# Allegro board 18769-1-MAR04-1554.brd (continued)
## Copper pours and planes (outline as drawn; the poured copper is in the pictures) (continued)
Net_26475 on BOTTOM_-MB (solid shape): 101.29,77.78 101.29,77.34 101.66,76.96 103.77,76.96 103.9,76.83 103.9,74.27 103.85,74.21 101.61,74.21 100.71,73.3 100.47,73.3 100.44,73.3 100.41,73.28 100.38,73.26 100.36,73.25 100.03,73.25 99.94,73.16 98.11,73.16 97.99,73.28 97.99,74.2 98.82,74.2 98.82,73.95 99.07,73.95 99.09,73.95 100.01,73.95 100.3,73.81 100.56,73.81 100.56,74.07 100.26,74.2 100.01,74.2 100.01,73.95 99.35,73.95 99.35,74.2 99.09,74.2 99.07,74.2 97.99,74.2 97.99,76.54 97.95,76.58 97.95,76.75 99.29,78.08 100.99,78.08
Net_26477 on BOTTOM_-MB (solid shape): 64.1,76 64.1,74.49 63.69,74.09 63.68,74.09 63.37,73.77 62.39,73.77 61.43,74.73 61.43,75.33 63.84,75.33 63.84,75.58 63.59,75.58 63.59,75.33 62.93,75.33 62.93,75.58 62.67,75.58 62.67,75.33 61.43,75.33 61.43,75.87 61.81,76.26 63.84,76.26
Net_26478 on BOTTOM_-MB (solid shape): outline of 206 points within 36.82,73.97 57.29,82.05
Net_26479 on BOTTOM_-MB (solid shape): 59.14,75.37 60.29,75.37 60.41,75.24 60.41,74.48 60.4,74.46 60.4,74.35 60.22,74.18 58.45,74.18 58.45,74.39 58.14,74.69 57.84,74.69 57.84,74.73 57.72,74.73 57.63,74.82 58.82,74.82 58.82,75.07 58.57,75.07 58.57,74.82 57.63,74.82 57.6,74.86 55.72,74.86 55.5,75.08 55.5,75.61 57.91,75.61 57.91,75.86 57.65,75.86 57.65,75.61 55.5,75.61 55.5,75.67 55.86,76.03 58.48,76.03
Net_26480 on BOTTOM_-MB (solid shape): 67.4,82.1 67.53,81.97 71.34,81.97 71.46,81.84 71.46,80.57 69.43,78.54 68.97,78.54 68.8,78.36 68.8,75.85 68.69,75.75 66.13,75.75 66,75.87 66,79.38 66,79.39 66.03,79.55 66,79.71 66,79.71 66,82.1 66.26,82.35 66.26,83.37 66.38,83.49 67.4,83.49
Net_26481 on BOTTOM_-MB (solid shape): 88.34,83.81 88.34,83.12 88.34,83.11 88.34,82.82 88.54,82.62 88.54,82.55 88.61,82.55 88.74,82.42 92.33,82.42 92.8,81.95 92.8,78.3 93.33,77.77 93.33,76.64 92.85,76.16 90.07,76.16 89.96,76.27 89.96,79.35 88.5,80.81 87.66,80.81 87.24,81.23 87.24,83.41 87.69,83.86 88.29,83.86
Net_26482 on BOTTOM_-MB (solid shape): 36.18,80.8 36.49,80.8 36.64,80.65 36.64,80.55 36.72,80.47 37.5,80.47 37.58,80.4 37.58,79.79 37.22,79.43 36.79,79.43 36.64,79.28 36.64,78.19 37.17,77.65 37.81,77.65 37.93,77.53 37.93,76.51 37.81,76.38 36.28,76.38 36.16,76.51 36.16,77.27 35.65,77.78 33.24,77.78 32.83,78.19 32.83,80.62 33.03,80.83 36.16,80.83
Net_26483 on BOTTOM_-MB (solid shape): 135.67,77.63 135.67,76.78 135.47,76.58 135.16,76.58 135.06,76.68 134.31,76.68 134.22,76.59 133.77,76.59 133.65,76.71 133.65,77.31 134.09,77.31 134.18,77.31 134.18,77.06 134.43,77.06 134.43,77.31 134.35,77.31 134.35,77.57 134.09,77.57 134.09,77.31 133.65,77.31 133.65,77.95 133.69,77.99 135.31,77.99
Net_26484 on BOTTOM_-MB (solid shape): 133.61,78.78 133.61,78.15 133.52,78.06 133.52,76.71 133.43,76.61 132.99,76.61 132.85,76.75 132.85,76.97 132.69,77.13 132.65,77.16 132.61,77.17 132.56,77.18 132.18,77.18 132.13,77.17 132.1,77.16 132.04,77.12 131.94,77.02 131.4,77.02 131.28,77.14 131.28,77.31 133.13,77.31 133.13,77.57 132.87,77.57 132.87,77.31 131.28,77.31 131.28,77.56 131.55,77.82 133.13,77.82 133.13,78.08 132.87,78.08 132.87,77.82 131.55,77.82 131.82,78.1 132.47,78.1 132.73,78.36 132.73,78.66 132.9,78.82 133.57,78.82
Net_26485 on BOTTOM_-MB (solid shape): 128.66,81.17 128.66,80.85 128.63,80.85 128.63,79.07 128.63,79.07 128.63,78.94 129.25,78.33 129.85,78.33 130.01,78.17 130.01,77.62 129.92,77.53 129.92,76.85 129.71,76.64 128.84,76.64 128.07,77.4 129.22,77.4 129.22,77.15 129.48,77.15 129.48,77.4 129.58,77.5 129.58,77.76 129.33,77.76 129.33,77.5 129.22,77.4 128.07,77.4 127.32,78.15 127.34,78.17 127.37,78.21 127.4,78.26 127.42,78.31 127.43,78.37 127.43,78.42 127.43,78.47 127.41,78.53 127.39,78.58 127.37,78.62 127.33,78.67 127.3,78.7 127.25,78.74 127.2,78.76 127.15,78.78 127.1,78.79 127.06,78.79 127.03,78.8 127.01,78.82 126.99,78.85 126.98,78.87 126.98,78.92 126.96,78.98 126.94,79.03 126.91,79.08 126.87,79.13 126.85,79.15 126.85,79.7 126.94,79.78 126.94,80.75 127.06,80.88 127.06,81.17 127.29,81.4 128.44,81.4
Net_26486 on BOTTOM_-MB (solid shape): outline of 133 points within 129.45,77.58 136.51,81.74
Net_26487 on BOTTOM_-MB (solid shape): outline of 85 points within 98.49,78.24 105.73,82.43
Net_26488 on BOTTOM_-MB (solid shape): 139.8,79.78 139.91,79.67 139.91,79.24 139.78,79.11 139.53,79.11 139.51,79.1 139.47,79.1 139.47,79.05 139.4,78.98 139.4,78.53 139.28,78.41 139.12,78.41 139.11,78.42 138.96,78.46 138.8,78.42 138.79,78.41 138.42,78.41 138.3,78.53 138.3,79.59 138.29,79.6 138.29,79.68 138.39,79.78 138.94,79.78
Net_26489 on BOTTOM_-MB (solid shape): 129.77,80.37 132.14,80.37 132.67,79.84 133.49,79.84 133.57,79.76 133.57,79.48 133.55,79.46 132.63,79.46 132,78.83 131.96,78.83 131.91,78.82 131.86,78.8 131.82,78.77 131.78,78.74 131.75,78.7 131.72,78.65 131.71,78.6 131.7,78.55 131.7,78.53 131.67,78.5 129.88,78.5 129.86,78.52 129.39,78.52 128.95,78.97 128.95,79.23 131.5,79.23 131.51,79.23 131.76,79.23 131.76,79.48 131.51,79.48 131.5,79.49 131.25,79.49 131.25,79.23 130.59,79.23 130.59,79.49 130.33,79.49 130.33,79.23 128.95,79.23 128.95,79.44 128.93,79.45 128.93,79.86 130.31,79.86 130.31,80.11 130.06,80.11 130.06,79.86 129.8,79.86 129.8,80.11 129.55,80.11 129.55,79.86 128.93,79.86 128.93,80.58 129.03,80.68 129.46,80.68
Net_26490 on BOTTOM_-MB (solid shape): 39.97,80.73 39.97,79.51 39.69,79.23 39.69,78.54 39.64,78.49 38.6,78.49 38.44,78.64 38.44,80.95 38.6,81.11 39.59,81.11
Net_26491 on BOTTOM_-MB (solid shape): 40.98,80.57 40.98,79.56 40.91,79.5 40.91,78.57 40.83,78.49 40.35,78.49 40.3,78.54 40.3,79.33 40.2,79.43 40.2,80.61 40.37,80.78 40.77,80.78
Net_26492 on BOTTOM_-MB (solid shape): outline of 111 points within 67.73,78.41 86.24,88.21
Net_26493 on BOTTOM_-MB (solid shape): 138.07,80.45 138.07,78.83 137.81,78.57 137.38,78.57 137.21,78.74 137.2,78.79 137.2,78.83 137.2,79.25 137.14,79.31 135.87,79.31 135.87,79.31 135.76,79.31 135.66,79.41 134.71,79.41 134.66,79.47 134.66,79.78 134.7,79.82 135.41,79.82 135.44,79.85 135.52,79.85 135.52,79.93 135.71,80.12 135.71,80.42 135.79,80.5 138.02,80.5
Net_26494 on BOTTOM_-MB (solid shape): outline of 1060 points within 167.93,78.93 178.76,86.34
Net_26495 on BOTTOM_-MB (solid shape): 126.94,81.56 126.94,80.93 126.81,80.8 126.81,79.84 126.66,79.68 125.74,79.68 125.01,80.42 125.01,81.62 125.08,81.69 126.81,81.69
Net_26496 on BOTTOM_-MB (solid shape): 138.49,81.91 140.43,81.91 140.66,81.68 140.68,81.63 140.68,80.75 140.05,80.11 138.33,80.11 138.24,80.2 138.24,80.55 138.03,80.76 136.03,80.76 135.89,80.9 139.46,80.9 139.52,80.87 139.78,80.87 139.78,81.12 139.52,81.12 139.46,81.15 139.21,81.15 139.21,80.9 138.55,80.9 138.55,81.15 138.29,81.15 138.29,80.9 135.89,80.9 135.59,81.2 135.59,82.34 135.78,82.53 137.88,82.53
Net_26497 on BOTTOM_-MB (solid shape): outline of 89 points within 109.21,79.92 117.82,87.37
Net_26498 on BOTTOM_-MB (solid shape): 122.11,84.26 122.11,82.57 122.18,82.5 122.16,82.47 122.25,81.99 122.74,81.99 122.75,82 122.79,82 123,82.21 123.13,82.21 123.15,82.22 123.58,82.22 123.59,82.23 123.97,82.23 123.98,82.22 124,82.25 124,82.77 124.1,82.86 127.59,82.86 127.75,82.71 127.75,81.92 127.57,81.74 126.99,81.74 126.99,81.81 126.87,81.81 126.86,81.82 125.03,81.82 125.02,81.81 124.93,81.81 124.93,81.72 124.88,81.67 124.88,80.96 124.5,80.58 119.48,80.58 119.09,80.98 119.09,84.23 119.39,84.54 121.83,84.54
Net_26499 on BOTTOM_-MB (solid shape): 100.5,86.03 100.79,86.03 100.81,86.01 100.81,85.5 101.21,85.11 101.21,84.44 101.09,84.32 100.57,84.32 100.56,84.3 100.49,84.3 100.49,84.23 100.15,83.89 100.15,82.83 99.85,82.53 99.16,82.53 98.21,81.57 95.12,81.57 94.89,81.8 94.89,82.02 95.68,82.8 96.25,82.8 96.53,83.08 96.53,84.6 96.79,84.86 100.83,84.86 100.83,85.11 100.58,85.11 100.58,84.86 96.79,84.86 97.3,85.38 98.64,85.38 98.8,85.54 98.8,85.85 99.06,86.11 100.42,86.11
Net_26500 on BOTTOM_-MB (solid shape): 90.11,86.06 90.11,84.82 90.16,84.76 90.46,84.76 90.47,84.75 92.74,84.75 93.26,84.23 95.75,84.23 95.95,84.03 95.95,83.29 94.49,81.83 93.9,81.83 93.13,82.61 88.73,82.61 88.61,82.73 88.61,83.2 93.71,83.2 93.71,83.45 94.37,83.45 94.37,83.2 94.63,83.2 94.66,83.21 94.92,83.21 94.92,83.47 94.66,83.47 94.63,83.45 93.46,83.45 93.46,83.2 88.61,83.2 88.61,83.24 88.53,83.32 88.53,83.85 89.17,83.85 89.17,84.51 88.53,84.51 88.53,86.11 88.66,86.24 89.93,86.24
Net_26501 on BOTTOM_-MB (solid shape): 131.8,83.17 131.8,82.33 131.54,82.07 129.05,82.07 128.69,82.43 128.69,83.13 128.86,83.3 131.41,83.3 131.41,83.33 131.65,83.33
Net_26502 on BOTTOM_-MB (solid shape): 73.16,86.74 75.87,86.74 77.15,85.46 78.67,85.46 78.94,85.19 78.94,84.24 78.92,84.21 78.9,84.15 78.88,84.09 78.87,84.03 78.87,83.97 78.88,83.91 78.9,83.85 78.92,83.79 78.94,83.76 78.94,83.35 78.92,83.32 78.9,83.27 78.88,83.21 78.87,83.15 78.87,83.09 78.88,83.03 78.89,82.97 78.92,82.91 78.94,82.87 78.94,82.82 78.82,82.71 76.57,82.71 75.52,83.76 73.15,83.76 72.41,84.5 73.49,84.5 73.49,84.75 74.15,84.75 74.15,84.5 74.41,84.5 74.46,84.5 75.63,84.5 75.63,84.76 75.37,84.76 75.37,84.5 74.71,84.5 74.71,84.76 74.46,84.76 74.41,84.75 73.24,84.75 73.24,84.5 72.41,84.5 72.24,84.67 69.62,84.67 69.49,84.8 69.49,85.63 76.46,85.62 76.46,85.88 76.2,85.88 76.2,85.62 75.11,85.62 75.11,85.88 74.59,85.88 74.59,85.63 73.5,85.63 73.5,85.88 73.24,85.88 73.24,85.63 69.49,85.63 69.49,85.84 69.65,86 70.92,86 70.98,86.06 71.05,86.06 71.05,86.85 71.11,86.91 72.99,86.91
Net_26503 on BOTTOM_-MB (solid shape): 128.32,85.78 132.01,85.78 132.26,85.53 132.26,84.31 131.52,83.57 131.41,83.57 131.41,83.61 128.87,83.61 128.87,83.57 128.38,83.57 128.13,83.32 124.09,83.32 124,83.41 124,84.55 124.15,84.7 126.89,84.7 126.89,84.71 126.92,84.74 126.99,84.74 126.99,84.8 127.09,84.91 127.09,85.04 131.79,85.04 131.79,85.3 131.53,85.3 131.53,85.04 127.09,85.04 127.09,86.38 127.15,86.44 127.67,86.44
Net_26504 on BOTTOM_-MB (solid shape): 138.52,85.63 138.52,85.4 138.44,85.33 137.66,85.33 137.66,85.24 137.6,85.17 137.6,84.34 137.89,84.04 137.89,83.49 137.75,83.35 134.65,83.35 134.51,83.49 134.51,84.94 134.77,85.2 136.97,85.2 137.02,85.26 137.08,85.26 137.08,85.32 137.43,85.67 137.48,85.67 137.52,85.68 138.47,85.68
Net_26505 on BOTTOM_-MB (solid shape): 139.41,86.42 139.41,85.53 139.46,85.47 139.46,85.27 140.05,85.27 140.3,85.02 140.3,84.51 140.04,84.26 139.41,84.26 138.65,85.02 138.65,86.16 138.62,86.18 138.62,86.33 137.85,86.33 137.76,86.42 137.76,86.67 137.88,86.8 139.03,86.8
Net_26506 on BOTTOM_-MB (solid shape): 92.83,87.08 94.09,87.08 94.17,87.16 94.17,87.16 94.27,87.26 94.65,87.26 94.65,87.22 94.97,87.22 95.06,87.12 95.06,86.87 96.29,85.64 96.29,84.98 95.97,84.67 93.49,84.67 93.28,84.88 90.52,84.88 90.28,85.13 90.28,85.31 93.71,85.31 93.71,85.56 94.37,85.56 94.37,85.31 94.63,85.31 94.66,85.32 95.83,85.32 95.83,85.58 95.58,85.58 95.58,85.32 94.92,85.32 94.92,85.58 94.66,85.58 94.63,85.56 93.46,85.56 93.46,85.31 90.28,85.31 90.28,86.12 90.43,86.27 91.85,86.27 92.01,86.43 92.01,87.17 92.1,87.26 92.65,87.26
Net_26507 on BOTTOM_-MB (solid shape): 139.43,88.52 139.43,87.25 139.18,87 137.73,87 137.68,86.95 137.68,86.95 137.56,86.82 137.56,86.81 137.12,86.38 137.12,86.31 137.09,86.27 137.06,86.22 137.04,86.17 137.03,86.12 137.02,86.07 137.02,86.01 137.03,85.96 137.05,85.9 137.07,85.86 137.1,85.81 137.12,85.79 137.12,85.57 136.93,85.37 133.72,85.37 133.41,85.68 133.41,86.73 136.11,86.73 136.11,86.99 136.77,86.99 136.77,86.73 137.02,86.73 137.3,87.09 137.3,87.13 139.04,87.13 139.04,87.38 138.79,87.38 138.79,87.13 137.3,87.13 137.3,87.34 137.05,87.34 136.77,86.99 135.85,86.99 135.85,86.73 133.41,86.73 133.41,86.98 133.68,87.25 135.85,87.25 135.88,87.28 135.98,87.38 135.98,87.61 136.25,87.88 137.25,87.88 137.26,87.89 138.79,87.89 138.79,87.64 139.04,87.64 139.04,87.89 139.09,87.89 139.09,88.15 138.84,88.15 138.84,87.89 137.26,87.89 137.46,88.09 137.98,88.09 138.47,88.59 139.37,88.59
Net_26508 on BOTTOM_-MB (solid shape): 126.12,88.02 126.12,86.98 125.93,86.78 125.93,86.67 125.9,86.64 125.9,85.82 125.86,85.79 125.43,85.79 125.43,85.8 125.31,85.93 125.31,86.29 125.4,86.38 125.4,86.49 125.4,87.03 125.25,87.18 124.07,87.18 123.95,87.3 123.95,87.41 125.68,87.41 125.68,87.67 125.43,87.67 125.43,87.41 123.95,87.41 123.95,87.86 124.02,87.93 124.57,87.93 124.61,87.93 124.67,87.93 124.71,87.93 125.28,87.93 125.42,88.06 126.07,88.06
Net_26509 on BOTTOM_-MB (solid shape): 101.7,87.52 101.7,86.98 101.52,86.79 100.92,86.79 100.84,86.71 100.84,86.59 100.84,86.59 100.84,86.3 100.77,86.24 99.01,86.24 98.49,85.71 96.42,85.71 95.3,86.83 95.29,86.83 95.19,86.94 95.19,87.19 95.53,87.19 95.55,87.21 99.84,87.21 99.84,87.15 99.86,87.1 99.88,87.05 99.91,87 99.94,86.96 99.99,86.92 100.03,86.89 100.08,86.87 100.14,86.85 100.19,86.84 100.25,86.84 100.3,86.85 100.36,86.87 100.41,86.89 100.45,86.92 100.49,86.96 100.53,87 100.56,87.05 100.58,87.1 100.59,87.15 100.6,87.21 100.6,87.26 100.59,87.3 101.31,87.3 101.31,87.56 101.05,87.56 101.05,87.3 100.59,87.3 100.59,87.32 100.57,87.37 100.55,87.42 100.51,87.47 100.47,87.51 100.43,87.54 100.38,87.57 100.33,87.59 100.27,87.6 100.22,87.6 100.16,87.6 100.11,87.59 100.06,87.57 100.01,87.54 99.96,87.51 99.93,87.47 99.89,87.42 99.87,87.37 99.85,87.32 99.84,87.26 99.84,87.21 95.55,87.21 95.62,87.28 95.97,87.28 96.54,87.85 101.38,87.85
Net_26510 on BOTTOM_-MB (solid shape): 140.3,88.5 140.3,88.4 140.42,88.27 140.45,88.25 140.58,88.12 140.91,88.12 141.01,88.02 141.01,87.61 140.85,87.46 140.45,87.46 140.2,87.2 140.2,86.77 140.32,86.65 140.32,86.42 140.24,86.34 139.62,86.34 139.54,86.42 139.54,87.18 139.56,87.2 139.56,87.89 140.11,87.89 140.11,87.64 140.36,87.64 140.36,87.89 140.31,87.89 140.31,88.15 140.06,88.15 140.06,87.89 139.56,87.89 139.56,88.62 139.62,88.68 140.12,88.68
Net_26511 on BOTTOM_-MB (solid shape): 131.36,88.3 131.36,88.24 131.3,88.15 131.19,88.16 130.57,87.86 131.19,87.57 131.3,87.58 131.36,87.49 131.36,86.52 131.25,86.42 128.05,86.42 127.9,86.57 127.9,87 127.97,87.07 127.97,87.69 128.04,87.94 127.92,88.17 127.91,88.2 127.92,88.24 128.21,88.52 131.13,88.52
Net_26512 on BOTTOM_-MB (solid shape): 116.43,88.51 116.43,88.3 116.41,88.26 116.39,88.2 116.38,88.15 116.38,88.09 116.39,88.03 116.4,87.98 116.43,87.93 116.46,87.88 116.5,87.84 116.54,87.8 116.59,87.77 116.64,87.75 116.7,87.73 116.74,87.73 116.75,87.72 119.4,87.72 120.32,88.64 120.76,88.64 120.9,88.5 120.9,88.02 120.61,87.74 120.61,86.57 120.49,86.44 118.42,86.44 117.66,87.2 116.64,87.2 116.09,87.76 112.62,87.76 112.11,87.25 111.8,87.25 111.55,87.5 111.34,87.5 110.51,87.5 110.17,87.5 110.11,87.51 109.59,87.51 109.31,87.79 110.33,87.79 110.34,87.79 111.51,87.79 111.51,88.04 111.25,88.04 111.25,87.79 110.59,87.79 110.59,88.04 110.34,88.04 110.33,88.04 110.08,88.04 110.08,87.79 109.31,87.79 109.23,87.88 109.23,88.52 109.43,88.72 116.23,88.72
Net_26513 on BOTTOM_-MB (solid shape): 79.77,88.27 79.77,86.95 79.62,86.8 78.89,86.8 78.81,86.89 73.27,86.89 72.86,87.3 76.46,87.3 76.46,87.51 79.09,87.51 79.09,87.5 79.09,87.25 79.35,87.25 79.35,87.5 79.34,87.51 79.34,87.77 79.09,87.77 79.09,87.51 76.46,87.51 76.46,87.56 76.2,87.56 76.2,87.3 75.11,87.3 75.11,87.56 74.59,87.56 74.59,87.3 73.5,87.3 73.5,87.56 73.24,87.56 73.24,87.3 72.86,87.3 72.74,87.42 72.74,87.6 72.74,87.62 72.73,87.66 72.71,87.7 72.69,87.73 72.65,87.76 72.65,88.02 79.34,88.02 79.34,88.28 79.09,88.28 79.09,88.02 72.65,88.02 72.65,88.04 73.09,88.48 79.56,88.48
Net_26514 on BOTTOM_-MB (solid shape): 135.75,88.4 135.75,87.71 135.62,87.59 134.05,87.59 134.05,88.5 134.15,88.6 134.18,88.6 134.35,88.78 135.37,88.78
OVP_UVP_REF_VDD on TOP: 155.74,30.54 155.88,30.67 156.13,30.67 156.34,30.47 156.34,30.23 156.68,29.88 156.68,29.51 156.59,29.41 156.59,29.16 156.47,29.04 155.98,29.04 155.74,29.28 ; 1 cut-out
OVP_UVP_REF_VDD on L3: 156.22,30.18 155.85,30.18 155.74,30.29 155.74,30.63 158.06,32.95 160.72,32.95 161.85,31.81 161.85,31.18 161.74,31.06 161.37,31.06 159.94,32.49 158.42,32.49 156.63,30.7 156.43,30.7 156.36,30.64 156.36,30.33
PCH_POPIRCOMP on TOP: 102.99,49.41 102.78,49.62 102.78,50.06 102.57,50.27 102.57,50.64 102.62,50.69 103.05,50.69 103.2,50.54 103.2,50.28 103.42,50.06 103.42,49.63 103.2,49.41
PS_ID_R2 on BOTTOM: 24.8,50.37 24.72,50.44 24.72,51.41 24.51,51.63 23.1,51.63 22.82,51.9 22.82,52.57 23.37,53.12 28.23,53.12 28.56,52.79 28.56,51.39 28.02,50.85 26.9,50.85 26.41,50.37
PWR_1D05V_PH on BOTTOM: 119.48,80.58 119.09,80.98 119.09,84.23 119.39,84.54 121.83,84.54 122.11,84.26 122.11,82.57 122.45,82.22 123.58,82.22 123.59,82.23 123.97,82.23 123.98,82.22 124,82.25 124,82.77 124.1,82.86 127.59,82.86 127.75,82.71 127.75,81.92 127.57,81.74 125.05,81.74 124.94,81.63 124.94,81.02 124.5,80.58
PWR_1D8V on BOTTOM: 27.38,44.88 27.32,44.94 27.32,45.92 27.6,46.2 28.43,46.2 29.55,47.33 29.55,49.36 29.68,49.48 31.71,49.48 32.07,49.13 32.07,47.17 31.84,46.94 30.57,46.94 30.14,46.51 30.14,45.37 30.13,45.37 30.13,45.08 29.94,44.88 ; 3 cut-outs
PWR_1D8V_PH on BOTTOM: 27.75,47.05 27.45,47.35 26.34,47.35 26.29,47.4 26.29,47.71 26.35,47.78 27.32,47.78 27.45,47.9 27.45,49.11 27.52,49.18 27.52,49.79 27.94,50.21 28.54,50.21 28.94,49.81 28.94,47.17 28.82,47.05
PWR_1D8V_PHASE on BOTTOM: 137.38,78.57 137.2,78.75 137.2,79.25 137.14,79.31 135.77,79.31 135.66,79.41 134.71,79.41 134.65,79.48 134.65,79.76 134.7,79.82 135.41,79.82 135.71,80.12 135.71,80.42 135.79,80.5 138.02,80.5 138.07,80.45 138.07,78.83 137.81,78.57
PWR_1D8V_PVDD on BOTTOM: 129.88,78.5 129.86,78.52 129.39,78.52 128.95,78.97 128.95,79.44 128.89,79.49 128.89,80.54 129.03,80.68 129.46,80.68 129.77,80.37 132.18,80.37 132.68,79.88 133.54,79.88 133.63,79.78 133.63,79.54 133.55,79.46 132.63,79.46 131.67,78.5 ; 4 cut-outs
PWR_1D8V_VGA on BOTTOM: 138.33,80.11 138.24,80.2 138.24,80.55 138.03,80.76 136.03,80.76 135.59,81.2 135.59,82.34 135.78,82.53 137.88,82.53 138.49,81.91 140.43,81.91 140.68,81.66 140.68,80.75 140.05,80.11 ; 2 cut-outs
PWR_1D8V_VGA on BOTTOM: 133.78,76.58 133.6,76.76 133.6,77.9 133.69,77.99 135.31,77.99 135.67,77.63 135.67,76.78 135.47,76.58 ; 1 cut-out
PWR_1D8V_VGA_FB on BOTTOM: 132.99,76.61 132.85,76.75 132.85,76.97 132.7,77.12 132.04,77.12 131.94,77.02 131.4,77.02 131.28,77.14 131.28,77.56 131.82,78.1 132.47,78.1 132.73,78.36 132.73,78.66 132.9,78.82 133.57,78.82 133.61,78.78 133.61,78.15 133.52,78.06 133.52,76.71 133.43,76.61 ; 2 cut-outs
PWR_1D8V_VIN on BOTTOM: 21.98,46.44 21.88,46.54 21.88,47.38 22.62,48.11 24.09,48.11 24.19,48.01 24.19,47.2 23.46,46.46 23.46,46.44 ; 1 cut-out
PWR_1D35V_BOOT on BOTTOM: 179.97,36.58 179.97,36.71 181.29,38.03 183.12,38.03 183.22,37.93 183.22,37.04 182.77,36.58 ; 1 cut-out
PWR_1D35V_BOOT_R on BOTTOM: 183.7,37.06 183.46,37.3 183.46,38.02 183.23,38.26 183.23,38.94 183.55,39.27 184.81,39.27 185.48,38.6 185.48,37.8 185.37,37.7 184.62,37.7 184.42,37.5 184.42,37.21 184.26,37.06 ; 2 cut-outs
PWR_1D35V_LDO_P5 on BOTTOM: 178.12,36.63 177.81,36.94 176.11,36.94 175.85,36.67 174.41,36.67 174.23,36.85 174.23,37.64 174.66,38.08 178.09,38.08 178.57,37.6 178.57,36.71 178.5,36.63
PWR_1D35V_PGOOD on BOTTOM: 176.7,33.35 176.7,33.36 175.69,33.36 175.35,33.7 175.35,34.37 175.36,34.38 175.36,34.78 175.52,34.95 175.93,34.95 176.32,34.55 177.66,34.55 178.07,34.96 178.57,34.96 178.65,34.88 178.65,34.02 178.63,34.02 178.55,33.94 177.43,33.94 177.41,33.91 177.26,33.91 ; 2 cut-outs
PWR_1D35V_PHASE on BOTTOM: 179.21,36.58 179.18,36.61 179.18,37.57 179.31,37.7 179.31,38.22 179.13,38.4 178.46,38.4 178.35,38.51 178.35,40.21 178.63,40.49 181.98,40.49 181.98,40.49 182.81,40.49 183.44,39.85 183.44,39.37 183.1,39.03 183.1,38.28 182.98,38.15 182.56,38.15 182.46,38.05 181.06,38.05 179.59,36.58 ; 1 cut-out
PWR_1V on BOTTOM: 133.72,85.37 133.41,85.68 133.41,86.98 133.68,87.25 135.85,87.25 135.98,87.38 135.98,87.61 136.25,87.88 137.25,87.88 137.46,88.09 137.98,88.09 138.47,88.59 139.37,88.59 139.43,88.52 139.43,87.25 139.18,87 137.73,87 137.68,86.95 137.68,86.95 137.56,86.82 137.56,86.81 137.12,86.38 137.12,85.57 136.93,85.37 ; 4 cut-outs
PWR_1V_FB on BOTTOM: 139.62,86.34 139.54,86.42 139.54,88.6 139.62,88.68 140.12,88.68 140.3,88.5 140.3,88.4 140.58,88.12 140.91,88.12 141.01,88.02 141.01,87.61 140.85,87.46 140.45,87.46 140.2,87.2 140.2,86.77 140.32,86.65 140.32,86.42 140.24,86.34 ; 1 cut-out
PWR_1V_PHASE on BOTTOM: 134.65,83.35 134.51,83.49 134.51,84.94 134.77,85.2 136.97,85.2 137.45,85.68 138.47,85.68 138.55,85.6 138.55,85.43 138.44,85.32 137.74,85.32 137.6,85.17 137.6,84.34 137.89,84.04 137.89,83.49 137.75,83.35
PWR_1V_PVDD on TOP: 141.26,86.01 141.08,86.19 141.08,87.69 141.19,87.79 143.98,87.79 144.36,88.17 144.85,88.17 144.92,88.1 144.92,86.45 144.88,86.42 142.3,86.42 141.9,86.01 ; 3 cut-outs
PWR_3D3V_FB2 on BOTTOM: 87.58,12.35 87.76,12.17 87.76,11.83 87.62,11.69 85.79,11.69 85.6,11.87 85.6,12.19 85.77,12.35
PWR_3D3V_PH on BOTTOM: 90.83,2.93 87.93,5.83 87.93,6.07 88.02,6.16 95.18,6.16 95.54,5.8 95.54,3.28 95.2,2.93
PWR_5V_FB on TOP: 78.07,2.24 77.94,2.37 77.94,3.46 77.86,3.54 77.54,3.54 77.4,3.69 77.4,3.96 77.47,4.03 78.51,4.03 78.57,3.97 78.57,3.11 78.73,2.95 79.25,2.95 79.37,2.83 79.37,2.36 79.25,2.24
PWR_5V_PH on BOTTOM: 71.59,2.6 71.08,3.1 71.08,6.91 70.19,7.8 70.19,8.82 70.57,9.2 71.21,9.2 71.34,9.07 71.34,8.56 71.86,8.04 75.61,8.04 76.93,6.73 76.93,6.31 76.83,6.21 75.78,6.21 75.59,6.41 74.76,6.41 74.26,5.9 74.26,3.87 72.99,2.6 ; 1 cut-out
PWR_5V_VCC on BOTTOM: 75.54,3.79 75.26,4.07 75.26,4.63 75.34,4.71 75.56,4.71 75.96,5.11 75.96,5.65 76.06,5.74 76.87,5.74 76.93,5.68 76.93,5.34 76.06,4.47 76.06,3.88 75.97,3.79
PWR_AD_A on TOP: 21.83,64.22 21.54,64.51 21.16,64.51 20.95,64.71 20.95,64.93 20.8,65.08 20.28,65.08 20.03,65.33 20.03,65.77 19.88,65.92 19.49,65.92 19.37,66.05 19.37,66.83 19.63,67.1 20.27,67.1 20.28,67.11 21.42,67.11 21.76,66.78 21.76,66.15 22.52,65.38 22.52,64.47 22.26,64.22 ; 2 cut-outs
PWR_AD_A on TOP: 28.46,68.31 28.23,68.53 28.23,68.69 28.23,68.69 28.18,68.74 28.18,69.4 27.78,69.8 27.78,69.8 27.63,69.95 27.63,70.84 27.55,70.92 27.55,70.93 26.83,71.66 26.83,72.79 26.16,73.46 26.16,76.65 26.46,76.95 27.81,76.95 28.04,76.72 28.04,73.99 28.18,73.84 28.18,71.73 28.27,71.65 30.16,71.65 30.18,71.63 30.51,71.63 30.62,71.52 30.62,68.94 29.99,68.31
PWR_AD_A on BOTTOM: 27.86,70.2 27.67,70.38 27.67,71.17 26.9,71.93 26.9,72.18 26.91,72.74 26.39,73.25 26.39,74.78 26.67,75.06 28.22,75.06 28.22,75.05 29.46,75.05 29.95,74.57 29.95,71.06 29.09,70.2 ; 2 cut-outs
PWR_AD_B on TOP: 134.12,7.67 133.97,7.82 133.97,9.4 133.82,9.56 132.73,9.56 132.42,9.86 132.42,10.52 132.58,10.67 138.72,10.67 139.66,11.61 139.66,13.24 139.92,13.49 141.06,13.49 141.34,13.21 141.34,11.09 141.34,11.09 141.34,9.62 140.4,8.68 139.84,8.68 139.49,8.34 136.58,8.34 135.92,7.67 ; 2 cut-outs
PWR_AD_B on TOP: 31.03,68.31 30.93,68.41 30.93,70.19 30.99,70.25 31.24,70.25 31.38,70.4 31.38,70.86 32.16,71.63 32.16,72.13 32.32,72.29 33.24,72.29 33.69,71.84 33.69,70.57 33.65,70.53 33.65,69.54 32.42,68.31
PWR_AD_B on BOTTOM: 132.52,3.24 132.13,3.63 132.13,7.31 132.56,7.73 132.96,8.14 132.96,12.18 134.92,14.14 141,14.14 141.16,14.3 141.16,17.07 141.36,17.28 142.3,17.28 142.63,16.95 142.63,13.82 142.37,13.56 142.37,10.54 142.07,10.24 139.61,10.24 138.33,11.53 136.13,11.53 135.85,11.25 135.85,7.64 135.45,7.23 135.45,4.32 135.68,4.09 135.68,3.39 135.52,3.24 ; 1 cut-out
PWR_AD_B on L7VCC: 25.86,28.95 25.98,29.06 25.98,67.46 30.75,72.23 33.54,72.23 34.29,71.48 34.29,68.38 33.96,68.05 33.96,57.84 34.77,57.03 34.77,53.07 32.72,51.01 32.72,49 33.94,47.77 33.94,26.74 27.54,20.33 27.44,20.33 25.72,18.61 25.72,17.98 33.28,10.42 33.96,10.42 33.97,10.42 39.73,10.42 39.81,10.42 39.87,10.48 40.81,11.42 83.19,11.42 84.14,10.47 86.53,10.47 87.12,9.89 116.66,9.89 117.26,9.29 121.14,9.29 122.58,7.84 124.8,7.84 125.88,6.76 134.28,6.76 135.33,5.71 135.33,2.99 134.25,1.91 121.11,1.91 119.56,3.46 23.61,3.46 17.33,9.74 17.33,20.45 25.83,28.95
PWR_CHG_BTST1_A on BOTTOM: 147.92,19.21 147.78,19.35 147.78,19.8 148.79,20.81 148.83,20.81 149.28,21.26 150.84,21.26 150.91,21.19 150.91,20.44 150.78,20.31 150,20.31 149.58,19.89 148.96,19.89 148.28,19.21
PWR_CHG_DCIN on TOP: 154.46,15.43 154.35,15.54 154.35,15.8 154.09,16.06 153.64,16.06 153.45,16.25 153.45,16.73 153.83,17.11 155.46,17.11 155.53,17.04 155.53,16.05 154.92,15.43 ; 1 cut-out
PWR_CHG_PHASE1 on TOP: 132.85,10.83 132.17,11.51 132.17,13.75 132.68,14.25 137.45,14.25 137.83,14.64 137.83,18.29 138.75,19.21 139.46,19.21 139.99,18.68 140.75,18.68 141.18,19.11 143.4,19.11 143.75,18.76 143.75,16.54 140.86,13.64 139.76,13.64 139.51,13.39 139.51,13.09 139.53,13.06 139.53,12.32 138.04,10.83
PWR_CHG_PHASE1 on BOTTOM: 137.69,14.44 137.22,14.92 137.22,17.9 138.62,19.31 142.91,19.31 143.58,18.65 143.58,17.79 143.2,17.4 141.34,17.4 141.01,17.07 141.01,14.52 140.93,14.44
PWR_CHG_PHASE2 on TOP: 129.45,12.6 128.97,13.09 128.97,14.05 130.33,15.41 130.8,15.41 131.06,15.67 131.06,20.84 131.19,20.96 133.88,20.96 134.06,20.78 134.06,15.72 133.74,15.4 132.57,15.4 131.84,14.67 131.84,13.16 131.28,12.6
PWR_CHG_PHASE2 on BOTTOM: 129.15,13.01 128.6,13.56 128.6,18.31 129.15,18.86 133.2,18.86 134.17,17.89 134.17,14.12 133.06,13.01
PWR_CHG_VBATIN on TOP: 120.09,9.87 119.33,10.63 118.63,10.63 118.26,11 118.26,12.41 119.88,14.02 121.26,14.02 121.35,13.93 121.35,9.97 121.24,9.87
PWR_CHG_VBATIN on BOTTOM: 115.25,10.61 115.14,10.72 115.14,11.87 115.38,12.11 118.24,12.11 118.91,12.78 118.91,12.78 120.61,12.78 121.18,12.21 121.18,10.82 120.98,10.61
PWR_CORE_VCCST on TOP: 47.25,67.33 47.09,67.49 47.09,67.61 46.8,67.9 46.8,68.52 46.5,68.82 46.5,69.18 46.76,69.44 50.07,69.44 50.19,69.33 50.19,68.67 50.19,68.67 50.19,67.88 50.01,67.7 48.48,67.7 48.11,67.33 ; 5 cut-outs
PWR_DCBATOUT_1D05V on BOTTOM: 124.09,83.32 124,83.41 124,84.55 124.15,84.7 126.89,84.7 126.89,84.71 127.09,84.91 127.09,86.38 127.15,86.44 127.67,86.44 128.32,85.78 132.01,85.78 132.26,85.53 132.26,84.31 131.52,83.57 128.38,83.57 128.13,83.32 ; 1 cut-out
PWR_DCBATOUT_1D35V on BOTTOM: 184.57,33.38 184.39,33.56 184.39,34.4 184.26,34.52 184.24,34.52 184.19,34.57 180.17,34.57 179.72,35.03 179.72,36.28 179.84,36.4 183.04,36.4 183.09,36.46 184.22,36.46 184.52,36.76 184.52,37.37 184.67,37.52 185.05,37.52 185.15,37.42 185.15,33.58 184.95,33.38
PWR_DCBATOUT_VCCGT on TOP: 39.59,51.87 39.33,52.13 39.33,56.19 39.71,56.57 40.86,56.57 41.11,56.32 41.11,53.9 40.47,53.27 40.47,52 40.35,51.87 ; 3 cut-outs
PWR_DCBATOUT_VCCGT on BOTTOM: 39.59,51.16 39.54,51.21 39.54,52.53 39.38,52.68 38.54,52.68 38.04,53.19 35.34,53.19 34.63,53.9 34.63,56.06 34.89,56.32 36.03,56.32 36.92,57.21 38.32,57.21 38.82,56.7 40.86,56.7 41.11,56.44 41.11,54.28 40.65,53.83 40.65,51.21 40.6,51.16 ; 7 cut-outs
PWR_DCBATOUT_VCCGT on L3: 38.87,55.89 40.2,55.89 40.47,55.61 40.47,51.8 40.2,51.52 39.08,51.52 38.6,52 38.6,55.61
PWR_DCBATOUT_VCCGT on L5: 39.36,55.68 40.35,55.68 40.63,55.4 40.63,51.77 40.45,51.59 39.61,51.59 39.13,52.08 39.13,55.45
PWR_DCBATOUT_VCCGT on L6: 39.69,55.58 40.4,55.58 40.58,55.4 40.58,51.87 40.4,51.69 39.66,51.69 39.33,52.02 39.33,55.22
PWR_DCBATOUT_VCCSA on TOP: 97.87,81.32 97.34,81.84 97.34,86.3 97.7,86.66 99.75,86.66 101.24,85.18 101.24,84.02 101.55,83.71 101.55,81.44 101.43,81.32 ; 4 cut-outs
PWR_DCBATOUT_VCCSA on BOTTOM: 95.12,81.57 94.89,81.8 94.89,82.02 95.68,82.8 96.25,82.8 96.53,83.08 96.53,84.6 97.3,85.38 98.64,85.38 98.8,85.54 98.8,85.87 99.09,86.16 100.26,86.16 100.37,86.16 100.5,86.03 100.79,86.03 100.81,86.01 100.81,85.5 101.21,85.11 101.21,84.44 101.09,84.32 100.57,84.32 100.15,83.89 100.15,82.83 99.85,82.53 99.16,82.53 98.21,81.57 ; 1 cut-out
PWR_DCBATOUT_VCOREA on TOP: 72.2,83.65 71.46,84.38 69.94,84.38 69.43,84.89 69.43,85.78 69.56,85.91 70.09,85.91 70.73,85.27 72.58,85.27 72.7,85.15 73.22,85.15 74,85.93 84.06,85.93 85.03,84.97 89.75,84.97 90.34,85.55 90.34,85.78 90.51,85.96 90.51,86.16 90.64,86.29 93.49,86.29 93.55,86.35 95.65,86.35 96.01,85.99 96.01,84.71 95.9,84.6 95.89,84.6 95.87,84.59 92.57,84.59 92.49,84.66 90.16,84.66 89.98,84.49 78.57,84.49 78.52,84.43 78.52,84.42 78.2,84.09 76.53,84.09 76.09,83.65 ; 8 cut-outs
PWR_DCBATOUT_VCOREA on BOTTOM: 76.57,82.71 75.52,83.76 73.15,83.76 72.24,84.67 69.62,84.67 69.49,84.8 69.49,85.84 69.65,86 70.92,86 71.02,86.1 71.04,86.12 71.04,86.84 71.11,86.91 72.99,86.91 73.16,86.74 75.87,86.74 77.15,85.46 78.67,85.46 78.94,85.19 78.94,82.82 78.82,82.71 ; 6 cut-outs
PWR_DCBATOUT_VCOREA on BOTTOM: 93.49,84.67 93.28,84.88 90.52,84.88 90.28,85.13 90.28,86.12 90.43,86.27 91.85,86.27 92.01,86.43 92.01,87.17 92.1,87.26 92.65,87.26 92.83,87.08 94.09,87.08 94.17,87.16 94.17,87.16 94.27,87.26 94.92,87.26 95.06,87.12 95.06,86.87 96.29,85.64 96.29,84.98 95.97,84.67 ; 3 cut-outs
PWR_DCBATOUT_VCOREA on L3: 69.94,86.14 75.98,86.14 76.44,85.68 76.44,84.84 76.09,84.49 69.84,84.49 69.48,84.84 69.48,85.68
PWR_DCBATOUT_VCOREA on L6: 73.37,84.88 76.11,84.88 76.11,84.89 94.74,84.89 95.7,85.85 95.7,86.82 95.32,87.19 74.55,87.19 73.02,85.67 73.02,85.22
PWR_DCBATOUT_VCOREA on L8: 69.56,85.91 76.11,85.91 76.39,85.63 76.39,84.82 75.96,84.38 69.91,84.38 69.41,84.89 69.41,85.76
PWR_DCBATOUT_VDDQ on TOP: 34.96,39.43 34.94,39.45 34.94,39.86 34.73,40.06 33.9,40.06 33.72,40.24 33.72,40.52 33.87,40.67 35.13,40.67 36.09,40.67 36.23,40.53 36.23,40.18 35.92,39.87 35.92,39.5 35.88,39.46 35.54,39.46 35.52,39.48 35.47,39.43 ; 1 cut-out
PWR_DCBATOUT_VDDQ on BOTTOM: 33.95,36.5 33.46,36.99 33.46,37.8 33.58,37.91 35.28,37.91 35.52,38.16 35.52,39.32 35.34,39.5 33.59,39.5 33.59,40.54 33.62,40.57 35.17,40.57 35.32,40.72 35.32,40.82 35.34,40.85 35.88,40.85 36.79,39.93 39.46,39.93 39.84,39.55 39.84,36.76 39.59,36.5
PWR_VCCGT_FB2 on BOTTOM: 45.1,58.27 44.97,58.4 44.67,58.4 44.62,58.35 44.08,58.35 43.98,58.45 43.98,58.86 44.08,58.96 45.02,58.96 45.3,59.24 45.3,59.62 45.38,59.7 45.83,59.7 45.86,59.67 45.86,58.43 45.71,58.27
PWR_VCCGT_SW on BOTTOM: 44.45,46.37 43.78,47.05 43.78,47.07 43.75,47.07 43.5,47.33 42.8,47.33 42.09,48.05 42.09,48.05 41.9,48.24 41.9,48.95 41.92,48.98 43.17,48.98 43.4,49.2 43.4,52.89 43.52,53.01 44.41,53.01 45.07,52.35 46.22,52.35 47.21,51.36 47.21,46.51 47.07,46.37
PWR_VCCSA_SW on TOP: 98.37,78.28 97.9,78.75 97.9,80.44 98.39,80.93 101.34,80.93 101.73,81.32 101.73,82.42 102.09,82.78 104.86,82.78 104.98,82.9 104.98,83.78 104.97,83.79 104.97,84.18 104.44,84.71 104.44,85.78 104.5,85.84 105.01,85.84 105.41,85.43 106.37,85.43 106.53,85.27 106.53,84.49 106.24,84.2 105.97,84.2 105.54,83.77 105.54,78.61 105.21,78.28 ; 1 cut-out
PWR_VCCSA_SW on BOTTOM: 99.15,78.24 98.49,78.89 98.49,80.54 98.99,81.04 98.99,82.19 99.24,82.43 105.42,82.43 105.73,82.12 105.73,79.61 105.72,79.6 105.72,79.07 104.89,78.24
PWR_VCORE_FB on BOTTOM: 51.37,60.03 51.24,60.15 51.24,62.01 51.4,62.16 51.78,62.16 51.9,62.03 51.9,60.15 51.78,60.03
PWR_VCORE_FB2 on BOTTOM: 53.07,59.11 52.87,59.31 52.87,59.7 52.97,59.8 53.51,59.8 53.76,60.05 53.76,60.71 53.66,60.81 52.26,60.81 52.18,60.89 52.18,61.37 52.24,61.42 54.22,61.42 54.32,61.32 54.32,60.81 54.51,60.62 55.43,60.62 55.51,60.53 55.51,60 55.33,59.81 54.31,59.81 54.22,59.72 54.22,59.24 54.09,59.11 ; 1 cut-out
PWR_VCORE_SWA on BOTTOM: 66.13,75.75 66,75.87 66,82.1 66.26,82.35 66.26,83.37 66.38,83.49 67.4,83.49 67.4,82.1 67.53,81.97 71.34,81.97 71.46,81.84 71.46,80.57 69.43,78.54 68.97,78.54 68.8,78.36 68.8,75.85 68.69,75.75
PWR_VCORE_SWB on BOTTOM: 90.07,76.16 89.96,76.27 89.96,79.35 88.5,80.81 87.66,80.81 87.24,81.23 87.24,83.41 87.69,83.86 88.29,83.86 88.34,83.81 88.34,83.12 88.34,83.11 88.34,82.82 88.74,82.42 92.33,82.42 92.8,81.95 92.8,78.3 93.33,77.77 93.33,76.64 92.85,76.16
PWR_VCORE_VCC on BOTTOM: 45.45,68.53 45.45,68.56 45.35,68.66 45.05,68.66 44.95,68.76 44.95,69.22 45.15,69.42 46.29,69.42 46.34,69.37 46.34,68.46 46.33,68.45 46.33,68.34 46.12,68.13 45.86,68.13 ; 1 cut-out
PWR_VCORE_VIN on TOP: 44.44,67.12 44.18,67.38 44.18,68.61 44.44,68.87 45.62,68.87 45.97,68.52 45.97,67.54 45.56,67.12 ; 1 cut-out
PWR_VDDQ on TOP: 45.31,37.7 45.3,37.72 44.34,37.72 42.48,39.58 42.48,43.46 42.63,43.62 44.79,43.62 45.05,43.87 45.05,44.25 45.43,44.63 47.59,44.63 48.98,43.24 48.98,38.66 48.02,37.7 ; 2 cut-outs
PWR_VDDQ on BOTTOM: 44.28,37.77 42.76,39.3 41.74,39.3 40.86,40.19 40.86,43.62 41.74,44.51 47.08,44.51 47.21,44.38 47.21,41.58 48.35,40.44 48.35,37.9 48.22,37.77 ; 2 cut-outs
PWR_VDDQ_PH on TOP: 32.36,40.78 32.2,40.95 32.2,41.63 32.39,41.83 35.4,41.83 35.57,41.66 35.57,40.89 35.46,40.78
PWR_VDDQ_PH on BOTTOM: 36.41,40.57 35.9,41.08 35.12,41.08 35.06,41.03 35.06,40.85 35.04,40.82 33.52,40.82 33.46,40.87 32.19,40.87 32.17,40.9 32.17,42.4 32.19,42.42 35.88,42.42 36.21,42.75 36.21,44.05 36.22,44.06 36.22,44.19 36.41,44.38 38.95,44.38 39.2,44.12 39.2,40.82 38.95,40.57
PWR_VDDQ_SNB on TOP: 33.02,42.16 32.87,42.3 32.87,42.49 33.02,42.64 33.67,42.64 34.01,42.98 34.01,43.32 34.1,43.4 35.9,43.4 36.35,42.95 36.35,42.31 36.2,42.16
PWR_VDDQ_VLDOIN on TOP: 32.73,37.03 32.6,37.16 32.6,38.16 32.95,38.5 34.04,38.5 34.28,38.27 34.28,37.31 34,37.03
PWR_VDDQ_VTT on BOTTOM: 30.09,38.79 30.57,39.28 30.96,39.28 31.08,39.15 31.08,39.04 31.84,38.28 32.35,38.28 32.52,38.46 32.52,39.22 32.55,39.25 32.7,39.25 32.73,39.22 32.73,38.61 32.78,38.56 33.24,38.56 33.31,38.64 33.31,39.22 33.34,39.25 33.49,39.25 33.52,39.22 33.52,38.66 33.49,38.64 33.49,38.46 32.85,37.83 32.85,37.39 32.73,37.27 30.69,37.27 30.56,37.13 29.73,37.13 29.67,37.19 29.67,38.7 29.76,38.79 ; 1 cut-out
PWR_VDDQ_VTTREF on TOP: 31.35,38.83 31.3,38.88 31.3,38.88 31.3,39.24 31.71,39.65 31.71,39.65 31.99,39.93 31.99,40.34 32.1,40.45 32.39,40.45 32.43,40.41 32.43,39.17 32.26,39 32.25,39 32.08,38.83 ; 1 cut-out
PWR_VGA_NVVDDS_BOOT1_A on BOTTOM: 149.87,29.22 149.29,29.8 149.29,30.49 149.14,30.64 149.14,30.94 149.33,31.13 150.46,31.13 150.66,30.93 150.66,29.37 150.51,29.22 ; 1 cut-out
PWR_VGA_NVVDDS_BOOT2_A on BOTTOM: 140.37,29.22 140.2,29.39 140.2,30.94 140.5,31.25 141.64,31.25 141.8,31.09 141.8,30.56 141.21,29.98 141.21,29.39 141.03,29.22 ; 1 cut-out
PWR_VGA_NVVDDS_PHASE1 on TOP: 148.98,32.87 148.63,33.23 148.63,37.77 148.65,37.8 148.65,38.44 148.17,38.92 148.17,41 148.37,41.2 148.37,41.94 148.35,41.97 148.35,42.83 148.83,43.31 152.84,43.31 153.17,42.98 153.17,41.31 151.96,40.09 151.96,33.15 151.68,32.87
PWR_VGA_NVVDDS_PHASE1 on BOTTOM: 149.69,32.82 148.74,33.78 148.74,38.83 148.27,39.3 148.27,43.09 149.09,43.91 153.02,43.91 153.3,43.62 153.3,39.23 152.78,38.71 152.07,38.71 151.75,38.38 151.75,33.2 151.37,32.82
PWR_VGA_NVVDDS_PHASE1 on BOTTOM: 146.77,30.38 146.75,30.41 146.75,30.92 146.88,31.04 148.42,31.04 148.53,31.15 148.83,31.15 148.93,31.04 148.93,30.49 148.83,30.38
PWR_VGA_NVVDDS_PHASE2 on TOP: 138.16,33.08 137.93,33.3 137.93,39.86 136.36,41.43 136.36,42.85 136.51,43.01 137.4,43.01 137.68,43.29 137.68,43.67 137.86,43.85 140.78,43.85 141.49,43.13 141.49,39.17 141.08,38.77 141.08,33.2 140.96,33.08
PWR_VGA_NVVDDS_PHASE2 on BOTTOM: 138.45,32.92 138.13,33.24 138.13,38.46 137.95,38.64 137.6,38.64 137.51,38.73 137.1,38.73 136.82,39.01 136.82,43.01 137.48,43.67 140.88,43.67 141.44,43.12 141.44,33.16 141.2,32.92
PWR_VGA_NVVDDS_VSEN1_N on TOP: 145.31,23.55 145.2,23.66 145.2,24.21 145.2,24.21 145.2,25.02 145.47,25.29 147.01,25.29 147.16,25.14 147.16,24.66 147.01,24.52 146.51,24.52 146.41,24.42 146.41,23.7 146.26,23.55 ; 2 cut-outs
PWR_VGA_NVVDDS_VSEN1_N on BOTTOM: 145.4,23.17 145.15,23.42 145.15,25.2 144.95,25.41 144.03,25.41 143.68,25.76 143.68,26.55 143.9,26.78 144.34,26.78 144.72,26.4 144.72,26.27 144.82,26.17 145.17,26.17 145.88,25.46 145.88,24.36 146.34,23.91 146.34,23.22 146.29,23.17 ; 2 cut-outs
PWR_VPP1D8V on BOTTOM: 33.97,29.57 33.9,29.65 33.9,31.65 34.02,31.78 35.42,31.78 35.67,31.53 37.12,31.53 37.68,32.09 40.22,32.09 40.45,31.86 40.45,30.33 39.92,29.8 37.45,29.8 37.22,29.57 ; 3 cut-outs
PWR_VPP1D8V_FB on TOP: 36.31,31.94 35.76,32.49 35.76,33.35 35.97,33.56 36.29,33.56 36.49,33.36 37.19,33.36 37.35,33.51 37.86,33.51 38.01,33.36 38.01,32.13 37.82,31.94 ; 2 cut-outs
SM_RCOMP_2 on TOP: 99.28,47 99.04,47.24 98.64,47.24 98.51,47.37 98.51,47.71 98.61,47.81 99.09,47.81 99.24,47.66 100.98,47.66 101.18,47.46 101.18,47.16 101.01,47
USB1_CC2 on BOTTOM: 23.36,58.71 23.25,58.81 23.25,59.05 23.46,59.27 23.72,59.27 23.86,59.41 23.98,59.41 24.39,59.81 24.62,59.81 24.64,59.79 24.64,59.58 23.77,58.71
USB_ADT on TOP: 24.52,72.22 24.47,72.27 24.47,74.03 23.81,74.69 23.61,74.69 22.66,75.64 22.66,75.97 22.85,76.17 23.26,76.17 23.42,76.32 23.42,77.89 23.57,78.03 25.78,78.03 26.06,77.76 26.06,73.38 25.7,73.02 25.53,73.02 25.5,72.99 25.5,72.98 25.32,72.8 25.31,72.8 25.08,72.57 25.08,72.29 25.01,72.22 ; 1 cut-out
USBCOMP on TOP: 105.3,62.79 105.12,62.97 105.12,63.17 105.4,63.45 105.63,63.45 105.83,63.66 106.31,63.66 106.39,63.58 106.39,63 106.18,62.79 ; 1 cut-out
XCLK_BIASREF on BOTTOM: 111.94,68.19 111.84,68.28 111.84,68.64 112.4,69.2 112.4,70.2 112.46,70.26 112.9,70.26 113,70.16 113,68.73 112.46,68.19

Small or netless copper shapes (teardrops, artwork), in the pictures only: 9567 on TOP_-MB, 1352 on L3_-MB, 1132 on L5_-MB, 1284 on L6_-MB, 1293 on L8_-MB, 11007 on BOTTOM_-MB, 4 on TOP, 7 on BOTTOM

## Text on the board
Ref Des/Silkscreen Bottom: F6501:1.1A/6V | X2401:32.768KHZ | WASP13-MB | MADE IN TAIWAN | 18769-SC | 448.0GW10.00SC | F5503:1.1A/24V | X1801:24MHZ | X7901:27MHZ
Ref Des/Silkscreen Top: F5502:1.1A/6V | F5701:1.1A/6V | X1802:32.768KHZ
User.28: 1V_CPU_CORE | 19V_DCBATOUT | GND | AUD_AGND
User.29: 3D3V_S5 | 1V_CPU_CORE | GND | AUD_AGND
User.30: PWR_AD_B | GND | AUD_AGND
User.31: GND | AUD_AGND
User.33: ByImpedance:100.0_DP@_REF_L10=("3.0/8.5(L9)")|_REF_L1=("3.0/8.5(L2)")|_REF_L6=("3.5/9.0(L4/L7)" "3.0/8.0(L5/L7)")|Type="DP"|imp="100.0"|_REF_L5=("3.0/8.0(L4/L6)" "3.5/9.0(L4/L7)") | ByImpedance:27.4_SE@_REF_L10=("11.0(L9)")|_REF_L1=("11.0(L2)")|_REF_L6=("11.0(L4/L7)" "9.0(L5/L7)")|Type="SE"|_REF_L3=("8.5(L2/L4)")|imp="27.4"|_REF_L5=("9.0(L4/L6)" "11.0(L4/L7)")|_REF_L8=("8.5(L7/L9)") | ByImpedance:33.0_SE@_REF_L10=("8.0(L9)")|_REF_L1=("8.0(L2)")|_REF_L6=("7.0(L5/L7)" "8.0(L4/L7)")|Type="SE"|_REF_L3=("6.5(L2/L4)")|imp="33.0"|_REF_L5=("8.0(L4/L7)" "7.0(L4/L6)")|_REF_L8=("6.5(L7/L9)") | ByImpedance:37.5_SE@_REF_L10=("6.5(L9)")|_REF_L1=("6.5(L2)")|_REF_L6=("6.5(L4/L7)" "5.5(L5/L7)")|Type="SE"|_REF_L3=("5.0(L2/L4)")|imp="37.5"|_REF_L5=("5.5(L4/L6)" "6.5(L4/L7)")|_REF_L8=("5.0(L7/L9)") | ByImpedance:40.0_SE@_REF_L10=("6.0(L9)")|_REF_L1=("6.0(L2)")|_REF_L6=("5.0(L5/L7)" "6.0(L4/L7)")|Type="SE"|_REF_L3=("4.5(L2/L4)")|imp="40.0"|_REF_L5=("5.0(L4/L6)" "6.0(L4/L7)")|_REF_L8=("4.5(L7/L9)") | ByImpedance:45.0_SE@_REF_L10=("4.5(L9)")|_REF_L1=("4.5(L2)")|_REF_L6=("4.0(L5/L7)" "4.5(L4/L7)")|Type="SE"|_REF_L3=("3.5(L2/L4)")|imp="45.0"|_REF_L5=("4.5(L4/L7)" "4.0(L4/L6)")|_REF_L8=("3.5(L7/L9)") | ByImpedance:48.0_SE@_REF_L10=("4.0(L9)")|_REF_L1=("4.0(L2)")|_REF_L6=("4.0(L4/L7)" "3.5(L5/L7)")|Type="SE"|_REF_L3=("3.01(L2/L4)")|imp="48.0"|_REF_L5=("3.5(L4/L6)" "4.0(L4/L7)")|_REF_L8=("3.01(L7/L9)") | ByImpedance:50.0_SE@_REF_L10=("3.5(L9)" "6.0/9.0/6.0(L8/L10)")|_REF_L1=("3.5(L2)" "6.0/9.0/6.0(L1/L3)")|_REF_L6=("3.5(L4/L7)" "3.0(L5/L7)")|Type="SE"|_REF_L3=("3.0(L2/L4)")|imp="50.0"|_REF_L5=("3.0(L4/L6)" "3.5(L4/L7)")|_REF_L8=("3.0(L7/L9)") | ByImpedance:60.0_DP@_REF_L10=("7.5/4.0(L9)")|_REF_L1=("7.5/4.0(L2)")|_REF_L6=("8.0/4.0(L4/L7)" "7.5/5.0(L5/L7)")|Type="DP"|_REF_L3=("7.0/4.5(L2/L4)")|imp="60.0"|_REF_L5=("7.5/5.0(L4/L6)" "8.0/4.0(L4/L7)")|_REF_L8=("7.0/4.5(L7/L9)") | ByImpedance:63.0_DP@_REF_L10=("7.0/4.0(L9)")|_REF_L1=("7.0/4.0(L2)")|_REF_L6=("7.0/6.0(L5/L7)" "7.5/4.0(L4/L7)")|Type="DP"|_REF_L3=("6.0/4.0(L2/L4)")|imp="63.0"|_REF_L5=("7.0/6.0(L4/L6)" "7.5/4.0(L4/L7)")|_REF_L8=("6.0/4.0(L7/L9)") | ByImpedance:70.0_DP@_REF_L10=("6.0/5.0(L9)")|_REF_L1=("6.0/5.0(L2)")|_REF_L6=("6.0/6.0(L5/L7)" "6.5/5.0(L4/L7)")|Type="DP"|_REF_L3=("5.0/4.0(L2/L4)")|imp="70.0"|_REF_L5=("6.0/6.0(L4/L6)" "6.5/5.0(L4/L7)")|_REF_L8=("5.0/4.0(L7/L9)") | ByImpedance:72.0_DP@_REF_L10=("5.5/4.5(L9)")|_REF_L1=("5.5/4.5(L2)")|_REF_L6=("5.5/5.0(L5/L7)" "6.0/4.5(L4/L7)")|Type="DP"|_REF_L3=("5.0/5.0(L2/L4)")|imp="72.0"|_REF_L5=("6.0/4.5(L4/L7)" "5.5/5.0(L4/L6)")|_REF_L8=("5.0/5.0(L7/L9)") | ByImpedance:75.0_DP@_REF_L10=("5.5/6.0(L9)")|_REF_L1=("5.5/6.0(L2)")|_REF_L6=("5.0/5.0(L5/L7)" "5.5/5.0(L4/L7)")|Type="DP"|_REF_L3=("4.5/4.0(L2/L4)")|imp="75.0"|_REF_L5=("5.5/5.0(L4/L7)" "5.0/5.0(L4/L6)")|_REF_L8=("4.5/4.0(L7/L9)") | ByImpedance:80.0_DP@_REF_L10=("4.5/5.0(L9)")|_REF_L1=("4.5/5.0(L2)")|_REF_L6=("5.0/5.0(L4/L7)" "4.5/5.0(L5/L7)")|Type="DP"|_REF_L3=("4.0/4.0(L2/L4)")|imp="80.0"|_REF_L5=("4.5/5.0(L4/L6)" "5.0/5.0(L4/L7)")|_REF_L8=("4.0/4.0(L7/L9)") | ByImpedance:81.0_DP@_REF_L10=("4.4/5.0(L9)")|_REF_L1=("4.4/5.0(L2)")|_REF_L6=("4.9/5.0(L4/L7)" "4.4/5.0(L5/L7)")|Type="DP"|_REF_L3=("3.9/4.0(L2/L4)")|imp="81.0"|_REF_L5=("4.9/5.0(L4/L7)" "4.4/5.0(L4/L6)")|_REF_L8=("3.9/4.0(L7/L9)") | ByImpedance:83.0_DP@_REF_L10=("4.0/4.5(L9)")|_REF_L1=("4.0/4.5(L2)")|_REF_L6=("4.5/8.0(L5/L7)" "4.5/4.5(L4/L7)")|Type="DP"|_REF_L3=("4.0/6.0(L2/L4)")|imp="83.0"|_REF_L5=("4.5/8.0(L4/L6)" "4.5/4.5(L4/L7)")|_REF_L8=("4.0/6.0(L7/L9)") | ByImpedance:85.0_DP@_REF_L10=("4.0/5.0(L9)")|_REF_L1=("4.0/5.0(L2)")|_REF_L6=("4.0/4.0(L4/L7)" "4.0/5.0(L5/L7)")|Type="DP"|_REF_L3=("3.5/4.0(L2/L4)")|imp="85.0"|_REF_L5=("4.0/4.0(L4/L7)" "4.0/5.0(L4/L6)")|_REF_L8=("3.5/4.0(L7/L9)") | ByImpedance:88.0_DP@_REF_L10=("3.5/5.0(L9)")|_REF_L1=("3.5/5.0(L2)")|_REF_L6=("4.0/8.0(L5/L7)" "4.0/4.5(L4/L7)")|Type="DP"|_REF_L3=("3.5/6.0(L2/L4)")|imp="88.0"|_REF_L5=("4.0/4.5(L4/L7)" "4.0/8.0(L4/L6)")|_REF_L8=("3.5/6.0(L7/L9)") | ByImpedance:90.0_DP@_REF_L10=("4.0/8.0(L9)" "6.5/4.0(L8)")|_REF_L1=("6.5/4.0(L3)" "4.0/8.0(L2)")|_REF_L6=("3.5/5.0(L5/L7)" "3.5/4.0(L4/L7)")|Type="DP"|_REF_L3=("3.5/7.0(L2/L4)")|imp="90.0"|_REF_L5=("3.5/4.0(L4/L7)" "3.5/5.0(L4/L6)")|_REF_L8=("3.5/7.0(L7/L9)") | ByImpedance:95.0_DP@_REF_L10=("3.5/8.0(L9)" "5.0/4.0(L8)")|_REF_L1=("3.5/8.0(L2)" "6.5/4.0(L4)")|_REF_L6=("3.0/5.0(L5/L7)" "4.5/4.0(L4/L8)" "5.5/4.0(L2/L9)" "3.5/5.5(L4/L7)")|Type="DP"|_REF_L3=("3.0/7.0(L2/L4)")|imp="95.0"|_REF_L5=("3.0/5.0(L4/L6)" "5.5/4.0(L2/L9)" "3.5/5.5(L4/L7)")|_REF_L8=("3.0/7.0(L7/L9)") | LayerIndex:nil | Source:10-1.0-8f.xls | artWorks:("_REF_L8" "_REF_L5" "_REF_L3" "_REF_L6" "_REF_L10" "_REF_L1") | gtImpOutlineUsed:BOARD GEOMETRY/PANEL_OUTLINE
User.34: Board Accuracy Check,Nov 24 09:20:29 2018,Passed | Dummy-Static-No Shape On Layer Check,Nov 24 09:20:30 2018,Passed | Split Plane Check,Sep 21 17:30:50 2018,Passed
User.38: This gerber is just for your reference to find the DP impedance traces in layer L1. | DP IMPEDANCE TABLE: L1 | * - Denotes that this Impedance | is NOT used | IMP(Ohm) | *60.0 | *63.0 | *70.0 | *72.0 | 75.0 | 80.0 | *81.0 | *83.0 | 85.0 | *88.0 | *90.0 | *95.0 | *100.0 | WIDTH(mils) | 7.5/4.0 | 7.0/4.0 | 6.0/5.0 | 5.5/4.5 | 5.5/6.0 | 4.5/5.0 | 4.4/5.0 | 4.0/4.5 | 4.0/5.0 | 3.5/5.0 | 6.5/4.0 | 4.0/8.0 | 3.5/8.0 | 3.0/8.5 | TYPE | DP | Ref. Plane | L2 | L3 | L4
User.40: This gerber is just for your reference to find the SE impedance traces in layer L1. | SE IMPEDANCE TABLE: L1 | * - Denotes that this Impedance | is NOT used | IMP(Ohm) | *27.4 | *33.0 | *37.5 | 40.0 | 45.0 | *48.0 | 50.0 | WIDTH(mils) | 11.0 | 8.0 | 6.5 | 6.0 | 4.5 | 4.0 | 3.5 | TYPE | SE | Ref. Plane | L2
User.42: This gerber is just for your reference to find the DP impedance traces in layer L3. | DP IMPEDANCE TABLE: L3 | * - Denotes that this Impedance | is NOT used | IMP(Ohm) | *60.0 | *63.0 | *70.0 | *72.0 | 75.0 | 80.0 | *81.0 | *83.0 | 85.0 | *88.0 | *90.0 | *95.0 | WIDTH(mils) | 7.0/4.5 | 6.0/4.0 | 5.0/4.0 | 5.0/5.0 | 4.5/4.0 | 4.0/4.0 | 3.9/4.0 | 4.0/6.0 | 3.5/4.0 | 3.5/6.0 | 3.5/7.0 | 3.0/7.0 | TYPE | DP | Ref. Plane | L2/L4
User.44: This gerber is just for your reference to find the SE impedance traces in layer L3. | SE IMPEDANCE TABLE: L3 | * - Denotes that this Impedance | is NOT used | IMP(Ohm) | *27.4 | *33.0 | *37.5 | 40.0 | 45.0 | *48.0 | 50.0 | WIDTH(mils) | 8.5 | 6.5 | 5.0 | 4.5 | 3.5 | 3.01 | 3.0 | TYPE | SE | Ref. Plane | L2/L4
User.45: Note:Refer to DRILL layer for ELLIPSE drill direction | FIGURE | SIZE | 8.0 | 10.0 | 16.0 | 20.0 | 128.0 | 142.0 | 150.0 | 30.0 | 38.0 | 46.0 | 48.0 | 65.0 | 86.0 | 158.0 | 40.0x20.0 | 44.0x20.0 | 63.0x24.0 | 97.0x36.0 | DRILL CHART: TOP to BOTTOM | ALL UNITS ARE IN MILS | PLATED | NON-PLATED | QTY | 996 | 3568 | 543 | 19 | 2 | 1 | 6 | 3 | 4 | This gerber is just for your reference to find the DP impedance traces in layer L10. | This gerber is just for your reference to find the DP impedance traces in layer L8. | This gerber is just for your reference to find the SE impedance traces in layer L10. | This gerber is just for your reference to find the SE impedance traces in layer L5. | This gerber is just for your reference to find the SE impedance traces in layer L6. | This gerber is just for your reference to find the SE impedance traces in layer L8. | This gerber is just for your reference to find the DP impedance traces in layer L5. | This gerber is just for your reference to find the DP impedance traces in layer L6. | DP IMPEDANCE TABLE: L10 | DP IMPEDANCE TABLE: L5 | DP IMPEDANCE TABLE: L6 | DP IMPEDANCE TABLE: L8 | SE IMPEDANCE TABLE: L10 | SE IMPEDANCE TABLE: L5 | SE IMPEDANCE TABLE: L6 | SE IMPEDANCE TABLE: L8 | * - Denotes that this Impedance | is NOT used | Model | WASP13-MB | PCB_NO | 18769 | VER. | SC | Layer | DRILL | L1 | L2GND | L3 | L4VCC | L5 | TMASK | TPLACE | TSILK | TSMD | Designer | FIZZ BIN | IMP(Ohm) | *27.4 | *60.0 | *33.0 | *63.0 | *37.5 | *70.0 | *72.0 | 40.0 | 45.0 | 75.0 | *48.0 | *80.0 | 80.0 | *40.0 | *81.0 | 50.0 | *83.0 | *45.0 | *75.0 | 85.0 | *88.0 | *90.0 | 90.0 | *95.0 | *50.0 | *100.0 | *85.0 | Date | 01/05/2019 | WIDTH(mils) | 11.0 | 6.5 | 6.0 | 4.5 | 4.0 | 3.5 | 7.5/4.0 | 8.5 | 9.0 | 7.0/4.0 | 5.0 | 6.0/5.0 | 7.0 | 5.5/4.5 | 5.5 | 5.5/6.0 | 3.01 | 4.5/5.0 | 3.0 | 4.4/5.0 | 4.0/4.5 | 4.0/5.0 | 3.5/5.0 | 4.0/8.0 | 6.5/4.0 | 3.5/8.0 | 5.0/4.0 | 3.0/8.5 | 7.0/4.5 | 7.5/5.0 | 8.0/4.0 | 6.0/4.0 | 7.0/6.0 | 5.0/5.0 | 4.5/4.0 | 6.0/6.0 | 4.0/4.0 | 6.5/5.0 | 3.9/4.0 | 5.5/5.0 | 6.0/4.5 | 4.0/6.0 | 3.5/4.0 | 3.5/6.0 | 3.5/7.0 | 3.0/7.0 | 4.9/5.0 | 4.5/8.0 | 4.5/4.5 | 3.0/5.0 | 5.5/4.0 | 3.5/5.5 | 3.0/8.0 | 3.5/9.0 | TYPE | SE | DP | Ref. Plane | L9 | L4/L6 | L4/L7 | L7/L9 | L5/L7 | L8 | L2/L9 | L4/L8 | BMASK | BPLACE | BSILK | BSMD | L10 | L6 | L7VCC | L9GND
